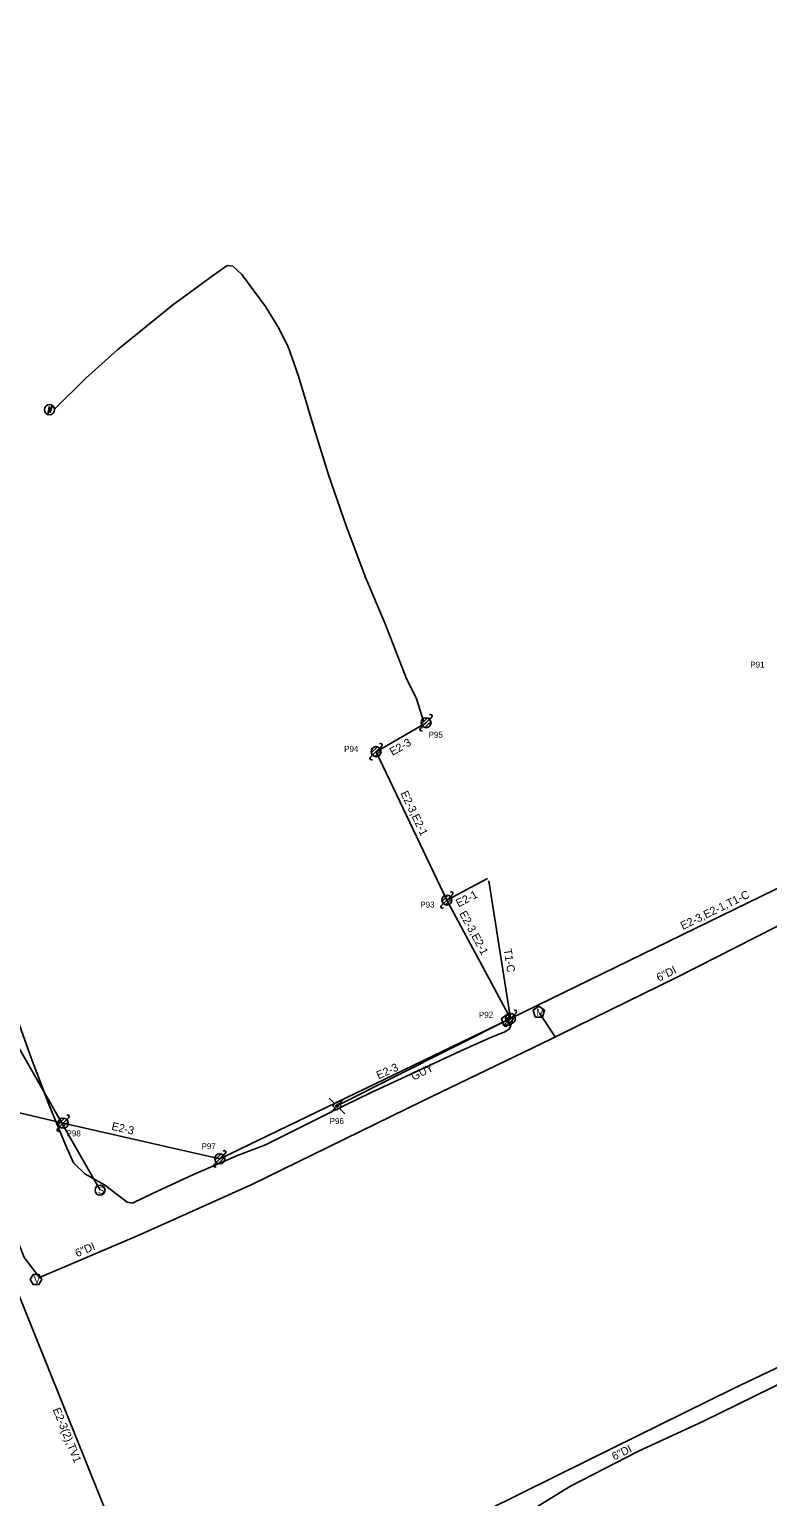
# Model space of a CAD drawing. Extents: x 1741604 to 1825760, y 1164229 to 1194908.
# Drawn here: x 1756010 to 1756379, y 1169455 to 1170189 of the extents above; entities that cross this region are included whole.
import ezdxf

# ---------------------------------------------------------------- set-up
doc = ezdxf.new("R2010")
doc.units = 0
for name, color, linetype in [('RD_EX_SU_Elec', 7, 'Continuous'), ('RD_EX_SU_H2O', 7, 'Continuous'), ('RD_EX_SU_Ovhd', 7, 'Continuous'), ('RD_EX_SU_Pole', 7, 'Continuous'), ('RD_EX_SU_Sewer', 7, 'Continuous'), ('RD_EX_SU_Telecom', 7, 'Continuous'), ('RD_EX_SU_TX_H2O', 7, 'Continuous'), ('RD_EX_SU_TX_Pole', 7, 'Continuous')]:
    doc.layers.add(name, color=color, linetype=linetype)

# ---------------------------------------------------------------- blocks, each defined once
blk = doc.blocks.new('SUE_SMH')
at = {"layer": 'RD_EX_SU_Sewer'}
blk.add_circle((0, 0), 2.5, dxfattribs=at)
blk.add_text('S', height=3.57, dxfattribs=at).set_placement((-1.1, -1.79))

msp = doc.modelspace()

# ---------------------------------------------------------------- linework, layer by layer
at = {"layer": 'RD_EX_SU_Elec'}
msp.add_lwpolyline([(1756022.72, 1169998.91), (1756038.36, 1170014.52), (1756054.32, 1170028.79), (1756081.79, 1170050.93), (1756102.19, 1170065.98), (1756109.03, 1170070.78), (1756111.93, 1170070.43), (1756116.38, 1170066.35), (1756128.3, 1170050.38), (1756134.86, 1170039.55), (1756137.29, 1170034.72), (1756139.43, 1170030.67), (1756144.81, 1170015.47), (1756151.96, 1169991.44), (1756159.74, 1169966.17), (1756168.64, 1169940.65), (1756178.37, 1169914.6), (1756188.01, 1169891.65), (1756198.92, 1169863.88), (1756203.62, 1169854.78), (1756207.42, 1169842.53)], dxfattribs=at)
msp.add_lwpolyline([(1756021.57, 1170000.8), (1756020.56, 1169997.35), (1756020.06, 1169999.22), (1756019.3, 1169996.4), (1756019.99, 1170000.3), (1756020.55, 1169998.37)], close=True, dxfattribs=at)
msp.add_circle((1756020.18, 1169998.74), 2.55, dxfattribs=at)
at = {"layer": 'RD_EX_SU_H2O'}
msp.add_line((1756265.27, 1169697.05), (1756273.03, 1169685.28), dxfattribs=at)
for points in [[(1755923.91, 1169771.92), (1755939.52, 1169740.59), (1755963.83, 1169686.41), (1755992.89, 1169612.51), (1756007.59, 1169575.08), (1756015.28, 1169564.93), (1756064.58, 1169585.92), (1756121.11, 1169611.4), (1756206.64, 1169653.11), (1756271, 1169684.14), (1756275.23, 1169686.24), (1756334.12, 1169715.1), (1756393.44, 1169745.19), (1756482.23, 1169790.32), (1756557.26, 1169827.38), (1756623.37, 1169859.51), (1756626.48, 1169861.14), (1756714.89, 1169903.8), (1756780.35, 1169935.86), (1756860.71, 1169974.61), (1756869.54, 1169979.15), (1756904.9, 1169996.7)], [(1756238.45, 1169448.31), (1756289.53, 1169473.78), (1756361.95, 1169509.43), (1756422.41, 1169538.26), (1756486.25, 1169569.02), (1756566.97, 1169608.84), (1756643.55, 1169646.48), (1756724.44, 1169685.4), (1756795.74, 1169719.73), (1756876.22, 1169758.33), (1756950.1, 1169794.65)]]:
    msp.add_lwpolyline(points, dxfattribs=at)
for points in [[(1756264.92, 1169700.66), (1756262.02, 1169698.55), (1756263.13, 1169695.14), (1756266.71, 1169695.14), (1756267.82, 1169698.55)], [(1756016.37, 1169563.98), (1756014.93, 1169566.48), (1756012.04, 1169566.48), (1756010.6, 1169563.98), (1756012.04, 1169561.48), (1756014.93, 1169561.48)]]:
    msp.add_lwpolyline(points, close=True, dxfattribs=at)
at = {"layer": 'RD_EX_SU_Ovhd'}
for p, q in [((1756183.51, 1169827.81), (1756208.52, 1169842.28)), ((1756183.51, 1169827.81), (1756218.93, 1169753.67)), ((1756250.77, 1169694.49), (1756422.89, 1169778.33)), ((1756218.93, 1169753.67), (1756239.29, 1169764.34)), ((1756250.77, 1169694.49), (1756239.88, 1169763.18)), ((1756218.93, 1169753.67), (1756250.77, 1169694.49)), ((1756163.97, 1169650.76), (1756250.77, 1169694.49)), ((1755964.26, 1169656.78), (1756027.03, 1169642.15)), ((1755964.26, 1169656.78), (1756076.65, 1169378.21))]:
    msp.add_line(p, q, dxfattribs=at)
for points in [[(1756105.37, 1169624.33), (1756250.77, 1169694.49)], [(1756027.03, 1169642.15), (1756105.37, 1169624.33)]]:
    msp.add_lwpolyline(points, dxfattribs=at)
at = {"layer": 'RD_EX_SU_Pole'}
for p, q in [((1756210.29, 1169844.05), (1756211.35, 1169845.11)), ((1756205.69, 1169839.45), (1756206.75, 1169840.51)), ((1756206.11, 1169841.64), (1756209.17, 1169844.7)), ((1756206.75, 1169840.51), (1756210.29, 1169844.05)), ((1756207.87, 1169839.87), (1756210.94, 1169842.93)), ((1756185.28, 1169829.58), (1756186.34, 1169830.64)), ((1756180.68, 1169824.98), (1756181.74, 1169826.04)), ((1756181.1, 1169827.17), (1756184.16, 1169830.23)), ((1756181.74, 1169826.04), (1756185.28, 1169829.58)), ((1756182.86, 1169825.4), (1756185.93, 1169828.46)), ((1756216.1, 1169750.84), (1756217.16, 1169751.9)), ((1756216.52, 1169753.02), (1756219.58, 1169756.08)), ((1756217.16, 1169751.9), (1756220.7, 1169755.44)), ((1756218.29, 1169751.25), (1756221.35, 1169754.32)), ((1756220.7, 1169755.44), (1756221.76, 1169756.5)), ((1756247.94, 1169691.66), (1756249, 1169692.73)), ((1756248.35, 1169693.85), (1756251.42, 1169696.91)), ((1756249, 1169692.73), (1756252.54, 1169696.26)), ((1756250.12, 1169692.08), (1756253.18, 1169695.14)), ((1756252.54, 1169696.26), (1756253.6, 1169697.32)), ((1756162.91, 1169651.82), (1756160.09, 1169654.65)), ((1756165, 1169651.88), (1756167.84, 1169654.72)), ((1756162.86, 1169649.71), (1756160.03, 1169646.89)), ((1756165.04, 1169649.7), (1756167.86, 1169646.87)), ((1756024.21, 1169639.32), (1756025.27, 1169640.38)), ((1756024.62, 1169641.5), (1756027.68, 1169644.57)), ((1756025.27, 1169640.38), (1756028.8, 1169643.92)), ((1756026.39, 1169639.74), (1756029.45, 1169642.8)), ((1756028.8, 1169643.92), (1756029.86, 1169644.98)), ((1756102.96, 1169623.68), (1756106.02, 1169626.74)), ((1756103.61, 1169622.56), (1756107.14, 1169626.1)), ((1756104.73, 1169621.91), (1756107.79, 1169624.98)), ((1756107.14, 1169626.1), (1756108.2, 1169627.16)), ((1756102.55, 1169621.5), (1756103.61, 1169622.56))]:
    msp.add_line(p, q, dxfattribs=at)
for points in [[(1756163.97, 1169648.64), (1756166.1, 1169650.76), (1756163.97, 1169652.88), (1756161.85, 1169650.76)], [(1756163.97, 1169650.05), (1756164.68, 1169650.76), (1756163.97, 1169651.47), (1756163.27, 1169650.76)]]:
    msp.add_lwpolyline(points, close=True, dxfattribs=at)
for centre in [(1756208.52, 1169842.28), (1756183.51, 1169827.81), (1756218.93, 1169753.67), (1756250.77, 1169694.49), (1756027.03, 1169642.15), (1756105.37, 1169624.33)]:
    msp.add_circle(centre, 2.5, dxfattribs=at)
for centre, start, end in [((1756210.82, 1169845.64), 315, 135), ((1756206.22, 1169838.92), 135, 315), ((1756185.81, 1169831.17), 315, 135), ((1756181.21, 1169824.45), 135, 315), ((1756221.23, 1169757.03), 315, 135), ((1756216.63, 1169750.31), 135, 315), ((1756253.07, 1169697.85), 315, 135), ((1756248.47, 1169691.13), 135, 315), ((1756029.33, 1169645.51), 315, 135), ((1756024.74, 1169638.79), 135, 315), ((1756107.67, 1169627.69), 315, 135), ((1756103.08, 1169620.97), 135, 315)]:
    msp.add_arc(centre, 0.75, start, end, dxfattribs=at)
at = {"layer": 'RD_EX_SU_Sewer'}
msp.add_lwpolyline([(1755472.28, 1170308.43), (1755562.01, 1170223), (1755684.15, 1170097.75), (1755848.2, 1169927.49), (1755891.42, 1169870.58), (1755920.4, 1169827.47), (1756045.49, 1169608.65)], dxfattribs=at)
at = {"layer": 'RD_EX_SU_Telecom'}
msp.add_line((1756250.16, 1169693.73), (1756250.77, 1169694.05), dxfattribs=at)
for points in [[(1756000.8, 1169703.32), (1756011.22, 1169674.31), (1756020.05, 1169651.16), (1756028.17, 1169631.24), (1756032.17, 1169622.39), (1756037.93, 1169616.8), (1756047.69, 1169611.24), (1756059.01, 1169602.72), (1756061.65, 1169602.2), (1756071.79, 1169606.93), (1756092.17, 1169616.56), (1756114.27, 1169626.03), (1756128.28, 1169631.31), (1756144.83, 1169639.6), (1756160.54, 1169647.48), (1756181.07, 1169657.5), (1756200.84, 1169666.63), (1756225.62, 1169678.09), (1756240.11, 1169684.7), (1756247.91, 1169687.72), (1756250.07, 1169689.15), (1756250.79, 1169690.65), (1756249.71, 1169693.12)], [(1756549.94, 1169589.96), (1756541.82, 1169587), (1756513.59, 1169574.05), (1756488.12, 1169561.24), (1756457.84, 1169546.06), (1756427.48, 1169532.35), (1756381.3, 1169509.82), (1756347.29, 1169493.22), (1756314.45, 1169477.96), (1756280.78, 1169460.79), (1756237.9, 1169434.39), (1756215.68, 1169416.31), (1756197.86, 1169399.08), (1756179.37, 1169372.51), (1756168.44, 1169336.07), (1756173.6, 1169292.17), (1756175.56, 1169279.77)]]:
    msp.add_lwpolyline(points, dxfattribs=at)
msp.add_lwpolyline([(1756249.08, 1169696.49), (1756246.23, 1169694.42), (1756247.32, 1169691.07), (1756250.84, 1169691.07), (1756251.93, 1169694.42)], close=True, dxfattribs=at)

# ---------------------------------------------------------------- block references
at = {"layer": 'RD_EX_SU_Sewer'}
msp.add_blockref('SUE_SMH', (1756045.49, 1169608.65), dxfattribs=at)

# ---------------------------------------------------------------- texts
at = {"layer": 'RD_EX_SU_H2O'}
for s, p in [('M', (1756263.55, 1169695.62)), ('V', (1756012.28, 1169562.11))]:
    msp.add_text(s, height=3.75, dxfattribs=at).set_placement(p)
at = {"layer": 'RD_EX_SU_Ovhd'}
for s, rotation, p in [('E2-3', 30.05095, (1756191.73, 1169825.64)), ('E2-3,E2-1', 295.53582, (1756195.64, 1169807.05)), ('E2-1', 27.65577, (1756224.73, 1169749.93)), ('E2-3,E2-1,T1-C', 25.96953, (1756336.95, 1169738.69)), ('E2-3,E2-1', 298.2807, (1756224.98, 1169746.95)), ('T1-C', 279.01019, (1756247.32, 1169729)), ('E2-3', 24.27674, (1756184.76, 1169664.01)), ('GUY', 26.74249, (1756202.28, 1169663.34)), ('E2-3', 347.18337, (1756050.97, 1169638.86)), ('E2-3(2),TV1', 291.97147, (1756021.77, 1169499))]:
    msp.add_text(s, height=4, rotation=rotation, dxfattribs=at).set_placement(p)
at = {"layer": 'RD_EX_SU_Telecom'}
msp.add_text('T', height=3.75, dxfattribs=at).set_placement((1756247.85, 1169691.27))
at = {"layer": 'RD_EX_SU_TX_H2O'}
for rotation, p in [(26.10606, (1756324.95, 1169712.83)), (23.06266, (1756034.06, 1169575.1)), (26.21276, (1756302.65, 1169473.55))]:
    msp.add_text('6"DI', height=4, rotation=rotation, dxfattribs=at).set_placement(p)
at = {"layer": 'RD_EX_SU_TX_Pole'}
for s, p in [('P91', (1756370.67, 1169869.81)), ('P95', (1756209.78, 1169834.79)), ('P94', (1756167.57, 1169827.72)), ('P93', (1756205.62, 1169749.87)), ('P92', (1756234.97, 1169694.78)), ('P96', (1756160.31, 1169641.72)), ('P98', (1756028.72, 1169635.5)), ('P97', (1756096.23, 1169629.12))]:
    msp.add_text(s, height=3, dxfattribs=at).set_placement(p)

doc.saveas('drawing.dxf')
